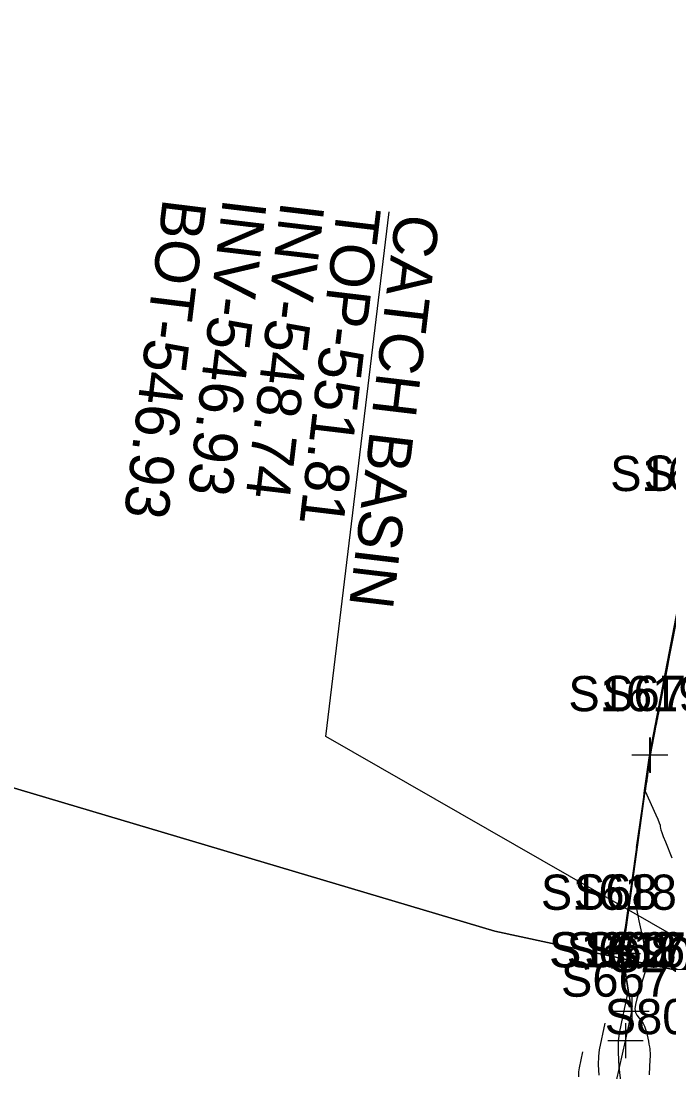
# Model space of a CAD drawing. Extents: x 1724534 to 1727318, y 657156 to 660047.
# Drawn here: x 1725360 to 1725433.7, y 659000.3 to 659119.7 of the extents above; entities that cross this region are included whole.
import ezdxf

# ---------------------------------------------------------------- set-up
doc = ezdxf.new("R2010")
doc.units = 0
for name, color, linetype in [('SURVEY - CONTOURS - Index with Text', 7, 'Continuous'), ('SURVEY - CONTOURS - Intermediate with optional Text', 7, 'Continuous'), ('SURVEY - DRAINAGE - Area Shapes', 7, 'Continuous'), ('SURVEY - DRAINAGE - Storm Sewer - Points - Numbers', 7, 'Continuous'), ('SURVEY - DRAINAGE - Storm Sewer Text', 7, 'Continuous'), ('SURVEY - DTM - Breaklines', 7, 'Continuous'), ('SURVEY - DTM - Breaklines - Points - Locators', 7, 'Continuous'), ('SURVEY - DTM - Breaklines - Points - Numbers', 7, 'Continuous'), ('SURVEY - MISCELLANEOUS - Bottom of MH and CB', 7, 'Continuous'), ('SURVEY - MISCELLANEOUS - Bottom of MH and CB - Points - Numbers', 7, 'Continuous'), ('SURVEY - NON-TRANSPORTATION - Features', 7, 'Continuous'), ('SURVEY - NON-TRANSPORTATION - Features - Points - Locators', 7, 'Continuous'), ('SURVEY - NON-TRANSPORTATION - Features - Points - Numbers', 7, 'Continuous')]:
    doc.layers.add(name, color=color, linetype=linetype)

msp = doc.modelspace()

# ---------------------------------------------------------------- linework, layer by layer
at = {"layer": 'SURVEY - CONTOURS - Index with Text'}
for points in [[(1725431.7, 659037.61), (1725434.48, 659051.96), (1725436.29, 659061.28), (1725436.74, 659062.97), (1725442.8, 659085.69), (1725443.22, 659087.41), (1725444.07, 659090.89), (1725444.53, 659092.81), (1725445.25, 659095.77), (1725445.72, 659097.71), (1725446.43, 659100.64), (1725446.91, 659102.6), (1725448.47, 659109.01), (1725448.78, 659110.32), (1725449.09, 659111.61), (1725449.91, 659115.12), (1725450.24, 659116.51), (1725451.06, 659120)], [(1725434.03, 659049.22), (1725433.65, 659047.27), (1725433.56, 659046.77), (1725433.48, 659046.37), (1725433.42, 659046.05), (1725433.37, 659045.81), (1725433.27, 659045.32), (1725433.23, 659045.09), (1725433.17, 659044.76), (1725433.09, 659044.35), (1725432.99, 659043.85), (1725432.6, 659041.88), (1725432.52, 659041.47), (1725432.46, 659041.15), (1725432.42, 659040.92), (1725432.33, 659040.45), (1725432.28, 659040.23), (1725432.22, 659039.91), (1725432.14, 659039.49), (1725432.04, 659038.98), (1725431.75, 659037.49), (1725431.58, 659036.64), (1725431.54, 659036.42), (1725431.52, 659036.34), (1725431.51, 659036.29), (1725431.5, 659036.23), (1725431.48, 659036.09), (1725431.45, 659035.87), (1725431.41, 659035.56), (1725431.29, 659034.64), (1725431.24, 659034.32), (1725431.23, 659034.22)], [(1725429.83, 659019.38), (1725429.99, 659018.61), (1725430.11, 659018.04), (1725430.24, 659017.43), (1725430.38, 659016.77), (1725430.53, 659016.07), (1725430.94, 659014.13), (1725431.07, 659013.48), (1725431.15, 659012.97), (1725431.18, 659012.6), (1725431.15, 659012.38), (1725431.03, 659011.97), (1725430.86, 659011.41), (1725430.72, 659010.94), (1725430.53, 659010.33), (1725429.99, 659008.56), (1725429.84, 659007.94), (1725429.79, 659007.43), (1725429.84, 659007.02), (1725429.99, 659006.72), (1725430.52, 659006.04), (1725430.71, 659005.77), (1725430.86, 659005.47), (1725430.99, 659005.14), (1725431.09, 659004.78), (1725431.31, 659003.77), (1725431.38, 659003.42), (1725431.44, 659003.13), (1725431.47, 659002.91), (1725431.49, 659002.74), (1725431.5, 659002.37), (1725431.5, 659002.11), (1725431.48, 659001.62), (1725431.44, 659000.89), (1725431.39, 658999.93)]]:
    msp.add_lwpolyline(points, dxfattribs=at)
at = {"layer": 'SURVEY - CONTOURS - Intermediate with optional Text'}
for points in [[(1725429.97, 659025.76), (1725430.74, 659031.2), (1725430.89, 659032.24), (1725431.41, 659035.97), (1725431.45, 659036.2), (1725431.48, 659036.4), (1725434.45, 659051.71), (1725436.31, 659061.26), (1725436.34, 659061.41), (1725437.37, 659065.25), (1725442.83, 659085.71), (1725443.32, 659087.76), (1725444.11, 659091.02), (1725444.62, 659093.11), (1725445.29, 659095.89), (1725445.8, 659098), (1725446.48, 659100.76), (1725446.99, 659102.88), (1725448.34, 659108.44), (1725448.76, 659110.2), (1725449.18, 659111.93), (1725449.94, 659115.18), (1725450.33, 659116.83), (1725451.08, 659120.05)], [(1725428.35, 659014.26), (1725428.65, 659016.34), (1725428.7, 659016.69), (1725429.32, 659021.01), (1725429.46, 659022.04), (1725430, 659025.82), (1725430.17, 659027.06), (1725430.69, 659030.68), (1725430.88, 659032.05), (1725431.38, 659035.63), (1725431.46, 659036.22), (1725431.49, 659036.37), (1725432.02, 659039.12), (1725432.58, 659041.99), (1725432.99, 659044.09), (1725433.53, 659046.91), (1725434.2, 659050.33)], [(1725429.04, 659009.33), (1725428.46, 659013.3), (1725428.43, 659013.48), (1725428.42, 659013.62), (1725428.41, 659013.73), (1725428.42, 659013.8), (1725428.45, 659014.06), (1725428.96, 659017.87), (1725429.04, 659018.44), (1725429.14, 659019.13), (1725429.31, 659020.35), (1725429.63, 659022.73), (1725429.71, 659023.34), (1725429.88, 659024.51), (1725430.3, 659027.62), (1725430.57, 659029.53), (1725430.98, 659032.53), (1725431.28, 659034.7), (1725431.48, 659036.14), (1725431.51, 659036.32), (1725432.23, 659040.01), (1725432.66, 659042.25), (1725433.18, 659044.91), (1725433.61, 659047.15), (1725434.13, 659049.81)], [(1725428.65, 659011.57), (1725428.36, 659013.52), (1725428.36, 659013.63), (1725428.36, 659013.77), (1725428.37, 659013.94), (1725428.4, 659014.15), (1725428.52, 659014.97), (1725428.64, 659015.84), (1725428.8, 659017.06), (1725428.9, 659017.8), (1725429.23, 659020.07), (1725429.33, 659020.78), (1725429.55, 659022.39), (1725429.92, 659025), (1725430.24, 659027.34), (1725430.6, 659029.94), (1725430.93, 659032.29), (1725431.32, 659035.07), (1725431.47, 659036.18), (1725431.5, 659036.35), (1725432.12, 659039.56), (1725432.62, 659042.12), (1725433.08, 659044.5), (1725433.57, 659047.03), (1725434.04, 659049.43)], [(1725433.69, 659047.39), (1725433.58, 659046.82), (1725433.5, 659046.39), (1725433.44, 659046.1), (1725433.41, 659045.95), (1725433.37, 659045.73), (1725433.34, 659045.57), (1725433.28, 659045.28), (1725433.2, 659044.84), (1725433.08, 659044.25), (1725432.63, 659041.93), (1725432.54, 659041.49), (1725432.46, 659041.07), (1725432.43, 659040.89), (1725432.4, 659040.75), (1725432.34, 659040.46), (1725432.25, 659040.02), (1725432.14, 659039.42), (1725431.79, 659037.63), (1725431.67, 659037.04), (1725431.59, 659036.62), (1725431.54, 659036.36), (1725431.52, 659036.27), (1725431.52, 659036.26), (1725431.49, 659036.05), (1725431.46, 659035.79), (1725431.25, 659034.31), (1725431.2, 659033.94), (1725431.17, 659033.68), (1725431.15, 659033.51), (1725431.14, 659033.45), (1725431.13, 659033.41), (1725431.13, 659033.37), (1725431.12, 659033.29), (1725431.1, 659033.17), (1725431.08, 659033.01), (1725430.96, 659032.15), (1725432.15, 659029.48), (1725432.37, 659028.97), (1725432.54, 659028.58), (1725432.64, 659028.31), (1725432.67, 659028.16), (1725432.69, 659027.94), (1725432.73, 659027.78), (1725432.84, 659027.47), (1725433.01, 659027.01), (1725433.25, 659026.4), (1725433.97, 659024.59)], [(1725428.92, 659009.03), (1725428.02, 659004.85), (1725427.89, 659003.8), (1725427.87, 659002.47), (1725427.96, 659000.84), (1725428.17, 658998.91)], [(1725426.38, 659005.8), (1725425.73, 659002.8), (1725425.63, 659002.05), (1725425.62, 659001.09), (1725425.69, 658999.92)], [(1725423.83, 659002.57), (1725423.43, 659000.75), (1725423.37, 659000.29), (1725423.37, 658999.71)]]:
    msp.add_lwpolyline(points, dxfattribs=at)
at = {"layer": 'SURVEY - DRAINAGE - Area Shapes'}
for points in [[(1725457.87, 659006.78), (1725413.86, 659016.26), (1725297.61, 659050.84), (1725314.04, 659296.61), (1725386.76, 659493.9), (1725483.4, 659755.23), (1725623.95, 659732.7), (1725676.22, 659724.33), (1725634.82, 659466.02), (1725543.32, 659353.72), (1725499.68, 659185.92), (1725479.09, 659106.74)], [(1725413.86, 659016.26), (1725457.87, 659006.78), (1725450.77, 658971.31), (1725440.16, 658905.18), (1725430.33, 658830.79), (1725434.82, 658762.28), (1725443.39, 658712.74), (1725438.08, 658666.38), (1725439.86, 658660.36), (1725446.98, 658655.62), (1725466.25, 658652.84), (1725462.78, 658619.36), (1725332.11, 658635.49), (1725320.81, 658709.21), (1725296.64, 658734.96), (1725279.1, 658753.63), (1725289.92, 658934.65), (1725297.61, 659050.84)]]:
    msp.add_lwpolyline(points, close=True, dxfattribs=at)
at = {"layer": 'SURVEY - DRAINAGE - Storm Sewer Text'}
msp.add_lwpolyline([(1725450.06, 659006.66), (1725394.64, 659038.38), (1725401.86, 659097.98)], dxfattribs=at)
at = {"layer": 'SURVEY - DTM - Breaklines'}
msp.add_lwpolyline([(1725548.52, 659521.48), (1725540.97, 659497.22), (1725536.85, 659481.64), (1725536.06, 659476.4), (1725532.19, 659451.33), (1725527.53, 659426.78), (1725520.29, 659402.81), (1725512.01, 659379.17), (1725506.04, 659356.07), (1725503.27, 659330.77), (1725496.16, 659306.74), (1725491.3, 659280.21), (1725484.67, 659256.07), (1725478.26, 659232.06), (1725472.37, 659207.66), (1725466.54, 659183.36), (1725459.12, 659159.23), (1725454.38, 659134.47), (1725448.67, 659109.98), (1725442.76, 659085.69), (1725436.26, 659061.29), (1725431.44, 659036.27), (1725428.27, 659013.72), (1725429.42, 659007.15)], dxfattribs=at)
at = {"layer": 'SURVEY - DTM - Breaklines - Points - Locators'}
for p, q in [((1725431.44, 659038.27), (1725431.44, 659034.27)), ((1725433.44, 659036.27), (1725429.44, 659036.27)), ((1725428.27, 659015.72), (1725428.27, 659011.72)), ((1725430.27, 659013.72), (1725426.27, 659013.72)), ((1725429.42, 659009.15), (1725429.42, 659005.15)), ((1725431.42, 659007.15), (1725427.42, 659007.15))]:
    msp.add_line(p, q, dxfattribs=at)
at = {"layer": 'SURVEY - NON-TRANSPORTATION - Features'}
for points in [[(1725429.42, 659007.15), (1725429.42, 659007.15), (1725428.42, 659013.69), (1725431.52, 659036.25), (1725436.43, 659061.26), (1725442.93, 659085.65), (1725448.79, 659109.95), (1725454.62, 659134.42), (1725460.64, 659158.85), (1725466.91, 659183.27), (1725472.48, 659207.63), (1725478.63, 659231.96), (1725484.87, 659256.01)], [(1725357.68, 658691.93), (1725363.17, 658711.31), (1725369.34, 658739.88), (1725375.28, 658769.31), (1725379.12, 658784.74), (1725384.76, 658809.11), (1725393.36, 658848.5), (1725405.65, 658900.8), (1725418.14, 658956.87), (1725428.71, 659003.82), (1725429.42, 659007.15)]]:
    msp.add_lwpolyline(points, dxfattribs=at)
at = {"layer": 'SURVEY - NON-TRANSPORTATION - Features - Points - Locators'}
for p, q in [((1725431.52, 659038.25), (1725431.52, 659034.25)), ((1725433.52, 659036.25), (1725429.52, 659036.25)), ((1725428.42, 659015.69), (1725428.42, 659011.69)), ((1725430.42, 659013.69), (1725426.42, 659013.69)), ((1725429.42, 659009.15), (1725429.42, 659005.15)), ((1725429.42, 659009.15), (1725429.42, 659005.15)), ((1725429.42, 659009.15), (1725429.42, 659005.15)), ((1725431.42, 659007.15), (1725427.42, 659007.15)), ((1725431.42, 659007.15), (1725427.42, 659007.15)), ((1725431.42, 659007.15), (1725427.42, 659007.15)), ((1725428.71, 659005.82), (1725428.71, 659001.82)), ((1725430.71, 659003.82), (1725426.71, 659003.82))]:
    msp.add_line(p, q, dxfattribs=at)

# ---------------------------------------------------------------- texts
at = {"layer": 'SURVEY - DRAINAGE - Storm Sewer - Points - Numbers'}
msp.add_text('S2041', height=4, dxfattribs=at).set_placement((1725426.82, 659011.59))
at = {"layer": 'SURVEY - DRAINAGE - Storm Sewer Text'}
for s, p in [('INV-546.93', (1725382.98, 659099.6)), ('INV-548.74', (1725389.55, 659099.27)), ('TOP-551.81', (1725395.96, 659098.78)), ('CATCH BASIN', (1725402.62, 659097.9))]:
    msp.add_text(s, height=5, rotation=263.195, dxfattribs=at).set_placement(p)
at = {"layer": 'SURVEY - DTM - Breaklines - Points - Numbers'}
for s, p in [('S66', (1725430.77, 659066.29)), ('S67', (1725426.06, 659041.27)), ('S68', (1725422.84, 659018.72)), ('S69', (1725424.02, 659012.15))]:
    msp.add_text(s, height=4, dxfattribs=at).set_placement(p)
at = {"layer": 'SURVEY - MISCELLANEOUS - Bottom of MH and CB'}
msp.add_text('BOT-546.93', height=5, rotation=262.9987, dxfattribs=at).set_placement((1725376.14, 659099.59))
at = {"layer": 'SURVEY - MISCELLANEOUS - Bottom of MH and CB - Points - Numbers'}
msp.add_text('S8003', height=4, dxfattribs=at).set_placement((1725426.35, 659004.56))
at = {"layer": 'SURVEY - NON-TRANSPORTATION - Features - Points - Numbers'}
for s, p in [('S1620', (1725426.97, 659066.26)), ('S1619', (1725422.22, 659041.25)), ('S1618', (1725419.09, 659018.69)), ('S1616', (1725420.02, 659012.15)), ('S1617', (1725420.13, 659012.15)), ('S668', (1725422.03, 659012.15)), ('S667', (1725421.38, 659008.82))]:
    msp.add_text(s, height=4, dxfattribs=at).set_placement(p)

doc.saveas('drawing.dxf')
